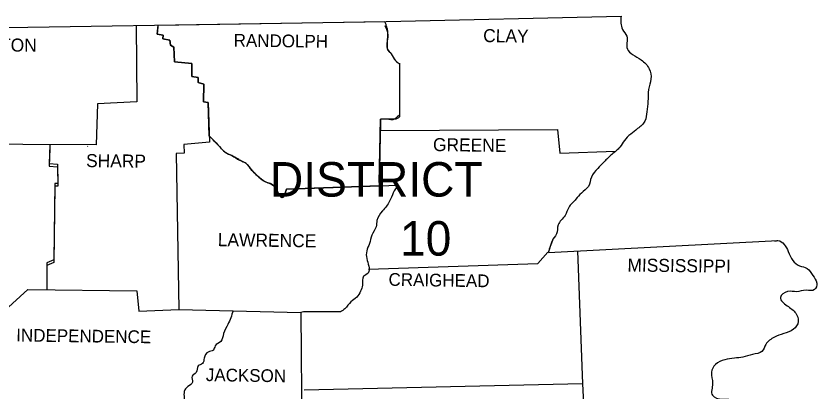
# Model space of a CAD drawing. Extents: x 3046 to 131673, y -8885 to 10756.
# Drawn here: x 105176 to 107768, y 9143 to 10358 of the extents above; entities that cross this region are included whole.
import ezdxf

# ---------------------------------------------------------------- set-up
doc = ezdxf.new("R2010")
doc.units = 0
for name, color, linetype in [('1', 7, 'Continuous'), ('2', 7, 'Continuous'), ('3', 7, 'Continuous')]:
    doc.layers.add(name, color=color, linetype=linetype)

msp = doc.modelspace()

# ---------------------------------------------------------------- linework, layer by layer
at = {"layer": '1'}
for p, q in [((105636.5, 10328.9), (106368.7, 10340.3)), ((105636.5, 10328.9), (106368.7, 10340.3)), ((106417.5, 10202.4), (106417.5, 10032.6)), ((106417.5, 10202.4), (106417.5, 10032.6)), ((106898.8, 9593.9), (106910.6, 9630.1)), ((106898.8, 9593.9), (106910.6, 9630.1)), ((106901.8, 9605.6), (106913.5, 9634)), ((106901.8, 9605.6), (106913.5, 9634))]:
    msp.add_line(p, q, dxfattribs=at)
for points in [[(101766.1, 10313), (103348.2, 10312), (104736.6, 10314.9), (106374.4, 10340.4), (107133.7, 10358)], [(101766.1, 10313), (103348.2, 10312), (104736.6, 10314.9), (106374.4, 10340.4), (107133.7, 10358)], [(105565.2, 10327.8), (105567.2, 10081.1), (105440, 10074.3), (105436.1, 9941.2), (104723.5, 9945.1)], [(105565.2, 10327.8), (105567.2, 10081.1), (105440, 10074.3), (105436.1, 9941.2), (104723.5, 9945.1)], [(105801.4, 9970.4), (105798.1, 10078.2), (105782.5, 10081.1), (105783.5, 10137.9), (105765.9, 10142.7), (105765.9, 10159.4), (105745.3, 10162.3), (105745.3, 10204.4), (105689.5, 10210.3), (105686.6, 10257.2), (105675.8, 10264.1), (105673.9, 10279.7), (105651.4, 10284.6), (105652.4, 10296.4), (105632.8, 10299.3), (105636.5, 10328.9)], [(105801.4, 9970.4), (105798.1, 10078.2), (105782.5, 10081.1), (105783.5, 10137.9), (105765.9, 10142.7), (105765.9, 10159.4), (105745.3, 10162.3), (105745.3, 10204.4), (105689.5, 10210.3), (105686.6, 10257.2), (105675.8, 10264.1), (105673.9, 10279.7), (105651.4, 10284.6), (105652.4, 10296.4), (105632.8, 10299.3), (105636.5, 10328.9)], [(105635.7, 10322.8), (105632.8, 10299.3), (105652.4, 10296.4), (105651.4, 10284.6), (105673.9, 10279.7), (105675.8, 10264.1), (105686.6, 10257.2), (105689.5, 10210.3), (105745.3, 10204.4), (105745.3, 10162.3), (105765.9, 10159.4), (105765.9, 10142.7), (105783.5, 10137.9), (105782.5, 10081.1), (105798.1, 10078.2), (105802.1, 9950), (105718.9, 9942.2), (105719.9, 9914.8), (105694.4, 9913.8), (105703.2, 9408.9), (106097.5, 9400.1), (106104.4, 8615.5), (105847.1, 8608.6), (105842.2, 8740.7)], [(105635.7, 10322.8), (105632.8, 10299.3), (105652.4, 10296.4), (105651.4, 10284.6), (105673.9, 10279.7), (105675.8, 10264.1), (105686.6, 10257.2), (105689.5, 10210.3), (105745.3, 10204.4), (105745.3, 10162.3), (105765.9, 10159.4), (105765.9, 10142.7), (105783.5, 10137.9), (105782.5, 10081.1), (105798.1, 10078.2), (105802.1, 9950), (105718.9, 9942.2), (105719.9, 9914.8), (105694.4, 9913.8), (105703.2, 9408.9), (106097.5, 9400.1), (106104.4, 8615.5), (105847.1, 8608.6), (105842.2, 8740.7)], [(106417.5, 10205.4), (106417.5, 10040)], [(106417.5, 10205.4), (106417.5, 10040)], [(106355.8, 10024.4), (106350.7, 9808.8), (106051.5, 9798.3)], [(106355.8, 10024.4), (106350.7, 9808.8), (106051.5, 9798.3)], [(106350.9, 9819.9), (106355.8, 10024.4), (106355.8, 9988.2), (106928.2, 9991.1), (106936, 9914.8), (107115.6, 9921.3)], [(106350.9, 9819.9), (106355.8, 10024.4), (106355.8, 9988.2), (106928.2, 9991.1), (106936, 9914.8), (107115.6, 9921.3)], [(105285.6, 9942), (105283.5, 9881.5), (105310.9, 9879.6), (105311.9, 9816.9), (105302.1, 9816.9), (105298.2, 9570.4), (105275.7, 9560.6), (105275.7, 9478.4)], [(105285.6, 9942), (105283.5, 9881.5), (105310.9, 9879.6), (105311.9, 9816.9), (105302.1, 9816.9), (105298.2, 9570.4), (105275.7, 9560.6), (105275.7, 9478.4)], [(105285.5, 9929.5), (105283.5, 9872.7), (105310.9, 9870.7), (105311.9, 9808.1), (105302.1, 9808.1), (105298.2, 9561.6), (105275.7, 9551.8), (105275.7, 9473.7)], [(105285.5, 9929.5), (105283.5, 9872.7), (105310.9, 9870.7), (105311.9, 9808.1), (105302.1, 9808.1), (105298.2, 9561.6), (105275.7, 9551.8), (105275.7, 9473.7)], [(105407.8, 9936.3), (105408.7, 9937.3)], [(105407.8, 9936.3), (105408.7, 9937.3)], [(106051.5, 9798.3), (106412.2, 9811)], [(106051.5, 9798.3), (106412.2, 9811)], [(106898.8, 9593.9), (107641.5, 9632)], [(106898.8, 9593.9), (107641.5, 9632)], [(106316.8, 9539.9), (106864.6, 9557.7), (106896.9, 9594.8)], [(106316.8, 9539.9), (106864.6, 9557.7), (106896.9, 9594.8)], [(106992.5, 9598.7), (107009.4, 9169.2), (107029.3, 8768.4)], [(106992.5, 9598.7), (107009.4, 9169.2), (107029.3, 8768.4)], [(105101.4, 9371.9), (105215, 9474.5), (105567.2, 9469.6), (105574.1, 9404), (105703.2, 9409)], [(105101.4, 9371.9), (105215, 9474.5), (105567.2, 9469.6), (105574.1, 9404), (105703.2, 9409)], [(106225.7, 9402.1), (106106.3, 9402.1), (106097.5, 9400.1)], [(106225.7, 9402.1), (106106.3, 9402.1), (106097.5, 9400.1)], [(107009.4, 9169.2), (106108.3, 9148.7)], [(107009.4, 9169.2), (106108.3, 9148.7)]]:
    msp.add_lwpolyline(points, dxfattribs=at)
for points in [[(106368.7, 10340.3), (106370.6, 10335.8), (106372.5, 10331.2), (106375.5, 10322), (106377.6, 10312.6), (106377.9, 10310.3), (106378.1, 10307.9), (106378.3, 10303.2), (106378.2, 10296.6), (106377.9, 10290), (106377.6, 10283.4), (106377.4, 10276.8), (106377.2, 10273.7), (106376.7, 10264.6), (106376.7, 10258.4), (106376.9, 10255.4), (106377.1, 10253.9), (106377.2, 10253.1), (106377.4, 10252.3), (106378.1, 10249.9), (106378.7, 10248.7), (106379.4, 10247.6), (106381, 10245.5), (106382.8, 10243.6), (106386.7, 10239.7), (106388.5, 10237.8), (106390.1, 10235.7), (106393.2, 10230.6), (106396.3, 10225.4), (106399.4, 10220.2), (106401, 10217.6), (106402.8, 10215.1), (106404.9, 10212.7), (106407.3, 10210.4), (106409.9, 10208.4), (106417.5, 10202.4)], [(106368.7, 10340.3), (106370.6, 10335.8), (106372.5, 10331.2), (106375.5, 10322), (106377.6, 10312.6), (106377.9, 10310.3), (106378.1, 10307.9), (106378.3, 10303.2), (106378.2, 10296.6), (106377.9, 10290), (106377.6, 10283.4), (106377.4, 10276.8), (106377.2, 10273.7), (106376.7, 10264.6), (106376.7, 10258.4), (106376.9, 10255.4), (106377.1, 10253.9), (106377.2, 10253.1), (106377.4, 10252.3), (106378.1, 10249.9), (106378.7, 10248.7), (106379.4, 10247.6), (106381, 10245.5), (106382.8, 10243.6), (106386.7, 10239.7), (106388.5, 10237.8), (106390.1, 10235.7), (106393.2, 10230.6), (106396.3, 10225.4), (106399.4, 10220.2), (106401, 10217.6), (106402.8, 10215.1), (106404.9, 10212.7), (106407.3, 10210.4), (106409.9, 10208.4), (106417.5, 10202.4)], [(107133.7, 10358), (107138.6, 10314.9), (107152.3, 10292.4), (107154.2, 10251.3), (107170.8, 10233.7), (107199.2, 10216.1), (107224.7, 10187.8), (107230.5, 10154.5), (107222.7, 10120.2), (107220.7, 10082.1), (107216.8, 10048.8), (107211, 10018.5), (107187.5, 9994), (107165, 9976.4), (107144.4, 9955.9), (107129.8, 9934.3), (107104.3, 9910.9), (107078.9, 9886.4), (107058.3, 9864.9), (107037.8, 9837.5), (107028, 9807.2), (107005.5, 9785.6), (106987.9, 9766.1), (106964.4, 9739.6), (106952.7, 9713.2), (106930.2, 9682.9), (106925.3, 9653.5), (106910.6, 9630.1), (106909.6, 9626.1)], [(107133.7, 10358), (107138.6, 10314.9), (107152.3, 10292.4), (107154.2, 10251.3), (107170.8, 10233.7), (107199.2, 10216.1), (107224.7, 10187.8), (107230.5, 10154.5), (107222.7, 10120.2), (107220.7, 10082.1), (107216.8, 10048.8), (107211, 10018.5), (107187.5, 9994), (107165, 9976.4), (107144.4, 9955.9), (107129.8, 9934.3), (107104.3, 9910.9), (107078.9, 9886.4), (107058.3, 9864.9), (107037.8, 9837.5), (107028, 9807.2), (107005.5, 9785.6), (106987.9, 9766.1), (106964.4, 9739.6), (106952.7, 9713.2), (106930.2, 9682.9), (106925.3, 9653.5), (106910.6, 9630.1), (106909.6, 9626.1)], [(106369.5, 10327.7), (106378.3, 10303.2), (106377.4, 10276.8), (106377.4, 10252.3), (106390.1, 10235.7), (106402.8, 10215.1), (106412.6, 10206.3)], [(106369.5, 10327.7), (106378.3, 10303.2), (106377.4, 10276.8), (106377.4, 10252.3), (106390.1, 10235.7), (106402.8, 10215.1), (106412.6, 10206.3)], [(106413.6, 10037.1), (106400.8, 10024.4), (106376.4, 10024.4), (106355.8, 10024.4)], [(106413.6, 10037.1), (106400.8, 10024.4), (106376.4, 10024.4), (106355.8, 10024.4)], [(106417.5, 10032.6), (106415.7, 10030.9), (106413.8, 10029.3), (106409.7, 10026.7), (106405.4, 10025), (106403.1, 10024.5), (106402, 10024.4), (106400.8, 10024.4), (106376.4, 10024.4), (106355.8, 10024.4)], [(106417.5, 10032.6), (106415.7, 10030.9), (106413.8, 10029.3), (106409.7, 10026.7), (106405.4, 10025), (106403.1, 10024.5), (106402, 10024.4), (106400.8, 10024.4), (106376.4, 10024.4), (106355.8, 10024.4)], [(106051.5, 9798.3), (106050.1, 9794.1), (106048.4, 9789.2), (106044.5, 9779.4), (106040.3, 9772.4), (106038.1, 9771.1), (106037, 9771.2), (106035.9, 9771.9), (106035.4, 9772.4), (106035, 9772.8), (106034.1, 9773.8), (106032.2, 9776), (106028.6, 9781.2), (106024.9, 9786.9), (106023, 9789.8), (106021.2, 9792.5), (106018.5, 9796.7), (106016, 9800.9), (106013.3, 9805.1), (106010.5, 9809.1), (106007.3, 9812.2), (106003.6, 9814.5), (105995.1, 9817.8), (105986.2, 9820.6), (105978.2, 9824.8), (105972.9, 9828.7), (105967.7, 9832.8), (105962.6, 9837), (105957.6, 9841.4), (105947.2, 9851.5), (105937.1, 9861.9), (105935.2, 9864.2), (105933.4, 9866.6), (105930.2, 9871.7), (105926.7, 9876.5), (105922.4, 9880.5), (105921.1, 9881.4), (105919.7, 9882.2), (105911.2, 9886.6), (105905.5, 9889.3), (105899.9, 9892.3), (105887.2, 9899.6), (105874.5, 9906.9), (105869, 9909.6), (105863.4, 9911.9), (105857.9, 9914.4), (105852.9, 9917.7), (105851.7, 9918.8), (105850.4, 9919.9), (105848, 9922.1), (105843.4, 9926.8), (105834.3, 9936.3), (105817.8, 9953.2), (105801.4, 9970.4)], [(106051.5, 9798.3), (106050.1, 9794.1), (106048.4, 9789.2), (106044.5, 9779.4), (106040.3, 9772.4), (106038.1, 9771.1), (106037, 9771.2), (106035.9, 9771.9), (106035.4, 9772.4), (106035, 9772.8), (106034.1, 9773.8), (106032.2, 9776), (106028.6, 9781.2), (106024.9, 9786.9), (106023, 9789.8), (106021.2, 9792.5), (106018.5, 9796.7), (106016, 9800.9), (106013.3, 9805.1), (106010.5, 9809.1), (106007.3, 9812.2), (106003.6, 9814.5), (105995.1, 9817.8), (105986.2, 9820.6), (105978.2, 9824.8), (105972.9, 9828.7), (105967.7, 9832.8), (105962.6, 9837), (105957.6, 9841.4), (105947.2, 9851.5), (105937.1, 9861.9), (105935.2, 9864.2), (105933.4, 9866.6), (105930.2, 9871.7), (105926.7, 9876.5), (105922.4, 9880.5), (105921.1, 9881.4), (105919.7, 9882.2), (105911.2, 9886.6), (105905.5, 9889.3), (105899.9, 9892.3), (105887.2, 9899.6), (105874.5, 9906.9), (105869, 9909.6), (105863.4, 9911.9), (105857.9, 9914.4), (105852.9, 9917.7), (105851.7, 9918.8), (105850.4, 9919.9), (105848, 9922.1), (105843.4, 9926.8), (105834.3, 9936.3), (105817.8, 9953.2), (105801.4, 9970.4)], [(105812.8, 9958.8), (105834.3, 9936.3), (105852.9, 9917.7), (105874.5, 9906.9), (105899.9, 9892.3), (105922.4, 9880.5), (105937.1, 9861.9), (105957.6, 9841.4), (105978.2, 9824.8), (106010.5, 9809.1), (106021.2, 9792.5), (106035.9, 9771.9), (106051.5, 9798.3)], [(105812.8, 9958.8), (105834.3, 9936.3), (105852.9, 9917.7), (105874.5, 9906.9), (105899.9, 9892.3), (105922.4, 9880.5), (105937.1, 9861.9), (105957.6, 9841.4), (105978.2, 9824.8), (106010.5, 9809.1), (106021.2, 9792.5), (106035.9, 9771.9), (106051.5, 9798.3)], [(106412.2, 9811), (106396.9, 9786.6), (106385.2, 9759.2), (106361.7, 9727.9), (106344.1, 9697.6), (106341.2, 9677), (106327.5, 9649.6), (106319.6, 9622.2), (106310.8, 9598.8), (106310.8, 9574.3), (106317.7, 9549.8), (106315.7, 9527.3), (106301, 9516.6), (106297.1, 9488.2), (106291.3, 9468.6), (106278.5, 9449.1), (106259.9, 9434.4), (106240.4, 9411.9), (106225.7, 9402.1)], [(106412.2, 9811), (106396.9, 9786.6), (106385.2, 9759.2), (106361.7, 9727.9), (106344.1, 9697.6), (106341.2, 9677), (106327.5, 9649.6), (106319.6, 9622.2), (106310.8, 9598.8), (106310.8, 9574.3), (106317.7, 9549.8), (106315.7, 9527.3), (106301, 9516.6), (106297.1, 9488.2), (106291.3, 9468.6), (106278.5, 9449.1), (106259.9, 9434.4), (106240.4, 9411.9), (106225.7, 9402.1)], [(107630.7, 9631), (107641.5, 9632), (107674.7, 9596.8), (107689.4, 9567.4), (107710.9, 9550.8), (107735.4, 9542), (107754, 9519.5), (107766.7, 9495), (107759.8, 9473.5), (107732.4, 9471.6), (107702.1, 9466.7), (107672.8, 9467.6), (107649.3, 9448.1), (107670.8, 9421.7), (107699.2, 9397.2), (107707, 9370.8), (107691.4, 9345.3), (107660, 9331.6), (107629.7, 9319.9), (107602.3, 9296.4), (107589.6, 9273.9), (107559.3, 9264.1), (107528, 9255.3), (107500.6, 9252.4), (107469.3, 9246.5), (107438.9, 9231.8), (107426.2, 9206.4), (107430.1, 9170.2), (107429.1, 9132.1), (107461.4, 9119.3), (107489.8, 9118.4), (107517.2, 9103.7), (107514.3, 9082.2), (107493.7, 9054.8), (107469.3, 9033.2), (107444.8, 9022.5), (107422.3, 9001.9), (107430.1, 8981.4), (107450.7, 8967.7), (107465.3, 8945.2), (107463.4, 8924.6), (107439.9, 8910), (107414.5, 8915.8), (107395.9, 8940.3), (107374.4, 8948.1), (107355.8, 8956.9), (107334.2, 8944.2), (107334.2, 8915.8), (107326.4, 8885.5), (107333.3, 8863), (107342.1, 8831.7), (107341.1, 8808.2), (107333.3, 8774.9), (107316.6, 8740.7), (107297.1, 8729.9), (107289.2, 8767.1), (107285.3, 8797.4), (107273.6, 8815), (107257.9, 8816), (107237.4, 8801.3), (107214.9, 8778.8), (107186.5, 8754.4), (107169.9, 8729.9), (107178.7, 8699.6), (107200.2, 8691.8), (107216.8, 8697.6), (107225.6, 8717.2), (107242.3, 8720.1), (107257.9, 8689.8)], [(107630.7, 9631), (107641.5, 9632), (107674.7, 9596.8), (107689.4, 9567.4), (107710.9, 9550.8), (107735.4, 9542), (107754, 9519.5), (107766.7, 9495), (107759.8, 9473.5), (107732.4, 9471.6), (107702.1, 9466.7), (107672.8, 9467.6), (107649.3, 9448.1), (107670.8, 9421.7), (107699.2, 9397.2), (107707, 9370.8), (107691.4, 9345.3), (107660, 9331.6), (107629.7, 9319.9), (107602.3, 9296.4), (107589.6, 9273.9), (107559.3, 9264.1), (107528, 9255.3), (107500.6, 9252.4), (107469.3, 9246.5), (107438.9, 9231.8), (107426.2, 9206.4), (107430.1, 9170.2), (107429.1, 9132.1), (107461.4, 9119.3), (107489.8, 9118.4), (107517.2, 9103.7), (107514.3, 9082.2), (107493.7, 9054.8), (107469.3, 9033.2), (107444.8, 9022.5), (107422.3, 9001.9), (107430.1, 8981.4), (107450.7, 8967.7), (107465.3, 8945.2), (107463.4, 8924.6), (107439.9, 8910), (107414.5, 8915.8), (107395.9, 8940.3), (107374.4, 8948.1), (107355.8, 8956.9), (107334.2, 8944.2), (107334.2, 8915.8), (107326.4, 8885.5), (107333.3, 8863), (107342.1, 8831.7), (107341.1, 8808.2), (107333.3, 8774.9), (107316.6, 8740.7), (107297.1, 8729.9), (107289.2, 8767.1), (107285.3, 8797.4), (107273.6, 8815), (107257.9, 8816), (107237.4, 8801.3), (107214.9, 8778.8), (107186.5, 8754.4), (107169.9, 8729.9), (107178.7, 8699.6), (107200.2, 8691.8), (107216.8, 8697.6), (107225.6, 8717.2), (107242.3, 8720.1), (107257.9, 8689.8)], [(105878.8, 9405.1), (105861.7, 9361), (105848, 9331.6), (105839.2, 9306.2), (105820.6, 9291.5), (105814.8, 9277.8), (105798.1, 9272), (105785.4, 9252.4), (105779.5, 9234.8), (105765.9, 9227), (105759, 9205.4), (105746.3, 9193.7), (105747.3, 9174.1), (105732.6, 9160.4), (105720.8, 9144.8), (105720.8, 9123.2), (105725.7, 9094.9), (105735.5, 9078.2), (105744.3, 9056.7), (105743.3, 9043), (105718.9, 9043), (105698.3, 9039.1)], [(105878.8, 9405.1), (105861.7, 9361), (105848, 9331.6), (105839.2, 9306.2), (105820.6, 9291.5), (105814.8, 9277.8), (105798.1, 9272), (105785.4, 9252.4), (105779.5, 9234.8), (105765.9, 9227), (105759, 9205.4), (105746.3, 9193.7), (105747.3, 9174.1), (105732.6, 9160.4), (105720.8, 9144.8), (105720.8, 9123.2), (105725.7, 9094.9), (105735.5, 9078.2), (105744.3, 9056.7), (105743.3, 9043), (105718.9, 9043), (105698.3, 9039.1)]]:
    msp.add_spline(points, degree=3, dxfattribs=at)

# ---------------------------------------------------------------- texts
at = {"layer": '2'}
for s, height, rotation, p in [('CLAY', 42.06, 359.2258, (106687.5, 10273.9)), ('CLAY', 42.06, 359.2258, (106687.5, 10273.9)), ('RANDOLPH', 41.09, 359.2583, (105880.3, 10259.2)), ('RANDOLPH', 41.09, 359.2583, (105880.3, 10259.2)), ('FULTON', 42.06, 359.4996, (105018.3, 10244.5)), ('FULTON', 42.06, 359.4996, (105018.3, 10244.5)), ('GREENE', 42.07, 359.2361, (106525.1, 9921.6)), ('GREENE', 42.07, 359.2361, (106525.1, 9921.6)), ('SHARP', 42.06, 359.3905, (105402.9, 9869.8)), ('SHARP', 42.06, 359.3905, (105402.9, 9869.8)), ('LAWRENCE', 42.07, 359.2678, (105828.9, 9614.2)), ('LAWRENCE', 42.07, 359.2678, (105828.9, 9614.2)), ('MISSISSIPPI', 42.062, 359.3097, (107154.2, 9532.2)), ('MISSISSIPPI', 42.062, 359.3097, (107154.2, 9532.2)), ('CRAIGHEAD', 41.09, 359.1159, (106381.3, 9486.2)), ('CRAIGHEAD', 41.09, 359.1159, (106381.3, 9486.2)), ('INDEPENDENCE', 41.081, 359.2187, (105176.9, 9306.2)), ('INDEPENDENCE', 41.081, 359.2187, (105176.9, 9306.2)), ('JACKSON', 41.08, 359.1352, (105790.3, 9178)), ('JACKSON', 41.08, 359.1352, (105790.3, 9178))]:
    msp.add_text(s, height=height, rotation=rotation, dxfattribs=at).set_placement(p)
at = {"layer": '3'}
for s, p in [('DISTRICT', (105998, 9774.3)), ('DISTRICT', (105998, 9774.3)), ('10', (106418.8, 9583.5)), ('10', (106418.8, 9583.5))]:
    msp.add_text(s, height=111.54, dxfattribs=at).set_placement(p)

doc.saveas('drawing.dxf')
